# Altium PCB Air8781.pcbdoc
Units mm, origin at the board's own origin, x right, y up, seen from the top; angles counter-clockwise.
Board outline 40.5 x 34.5 mm, 2 copper layers (Top Layer, Bottom Layer); 1 components, 0 nets, 12 pads, 0 vias.
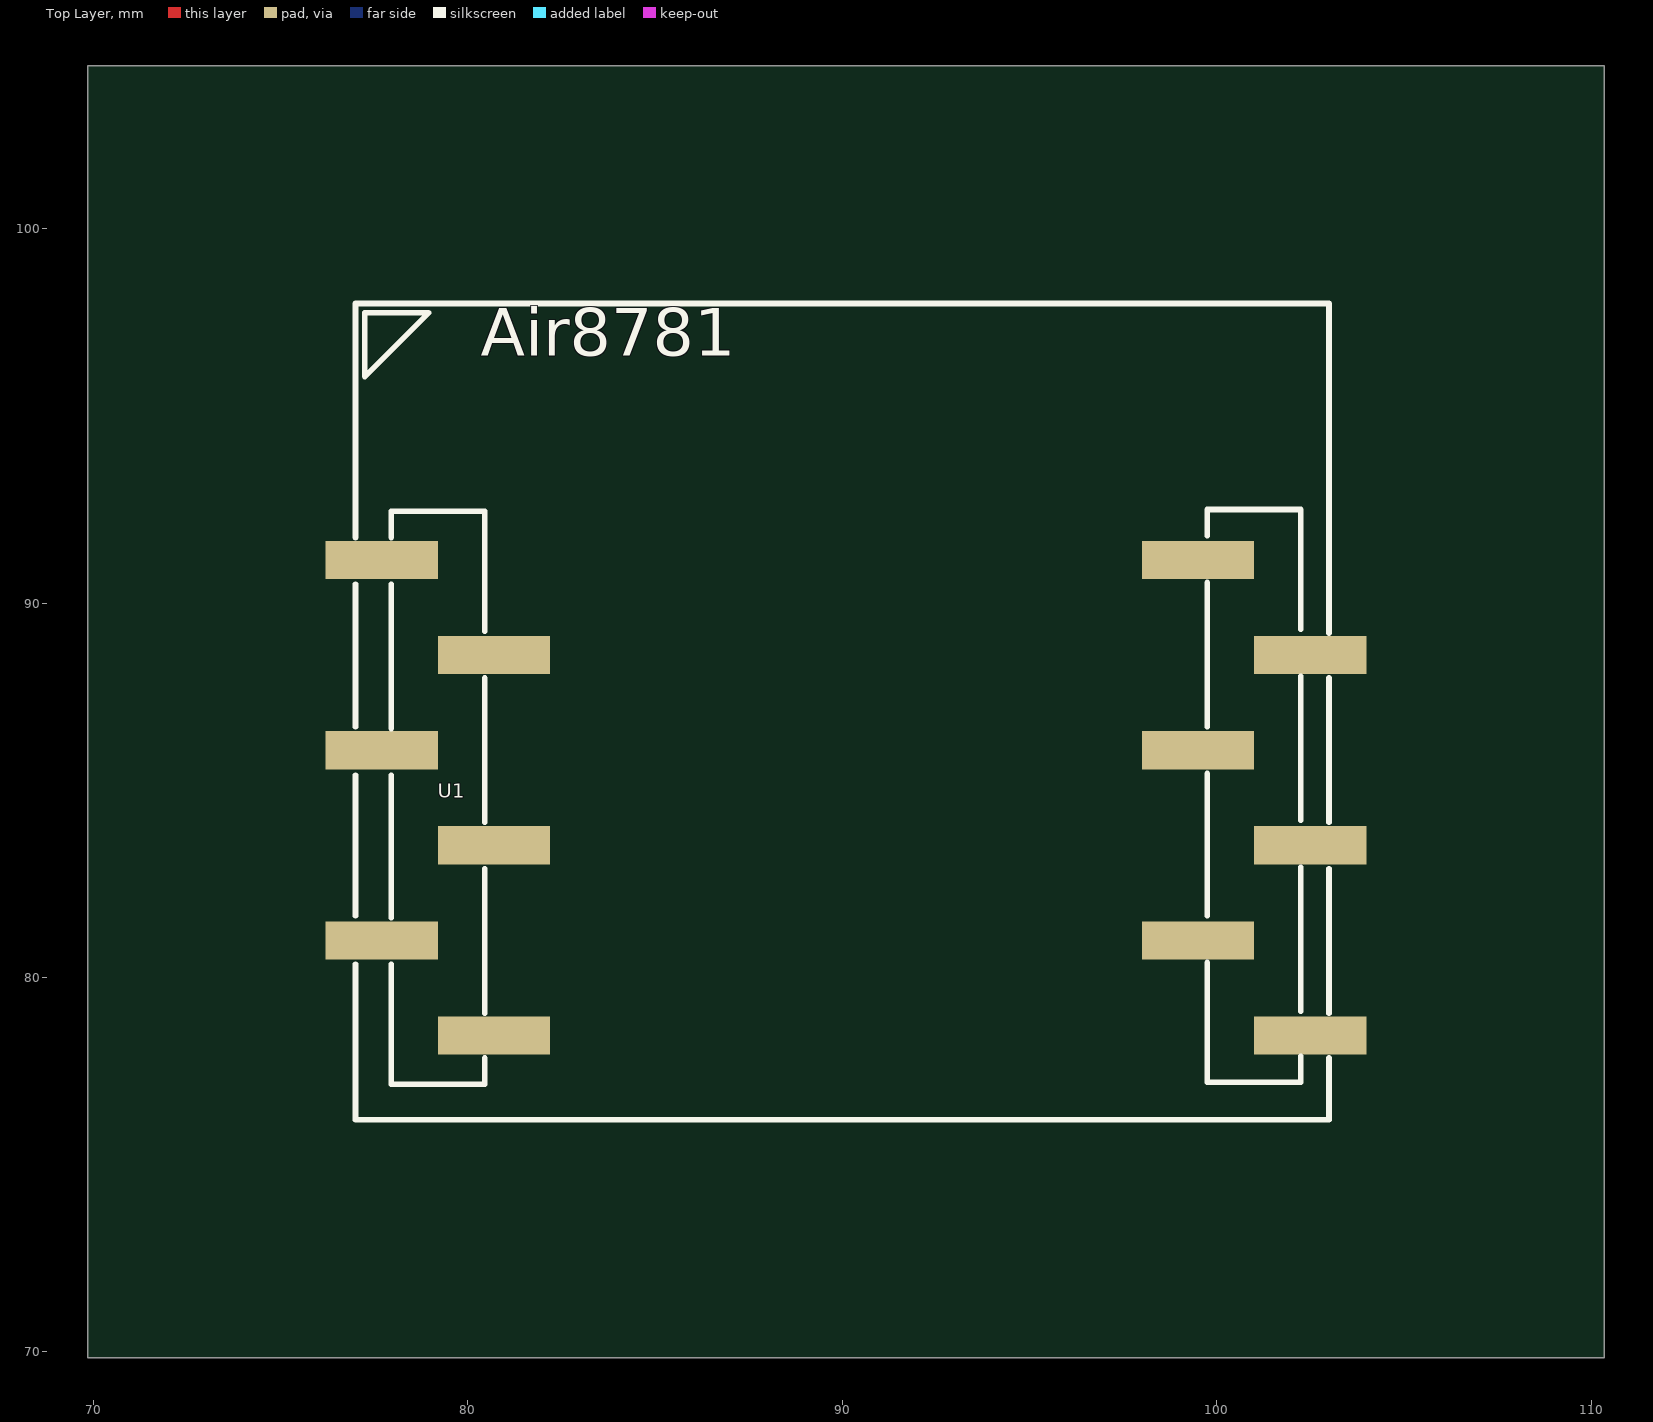
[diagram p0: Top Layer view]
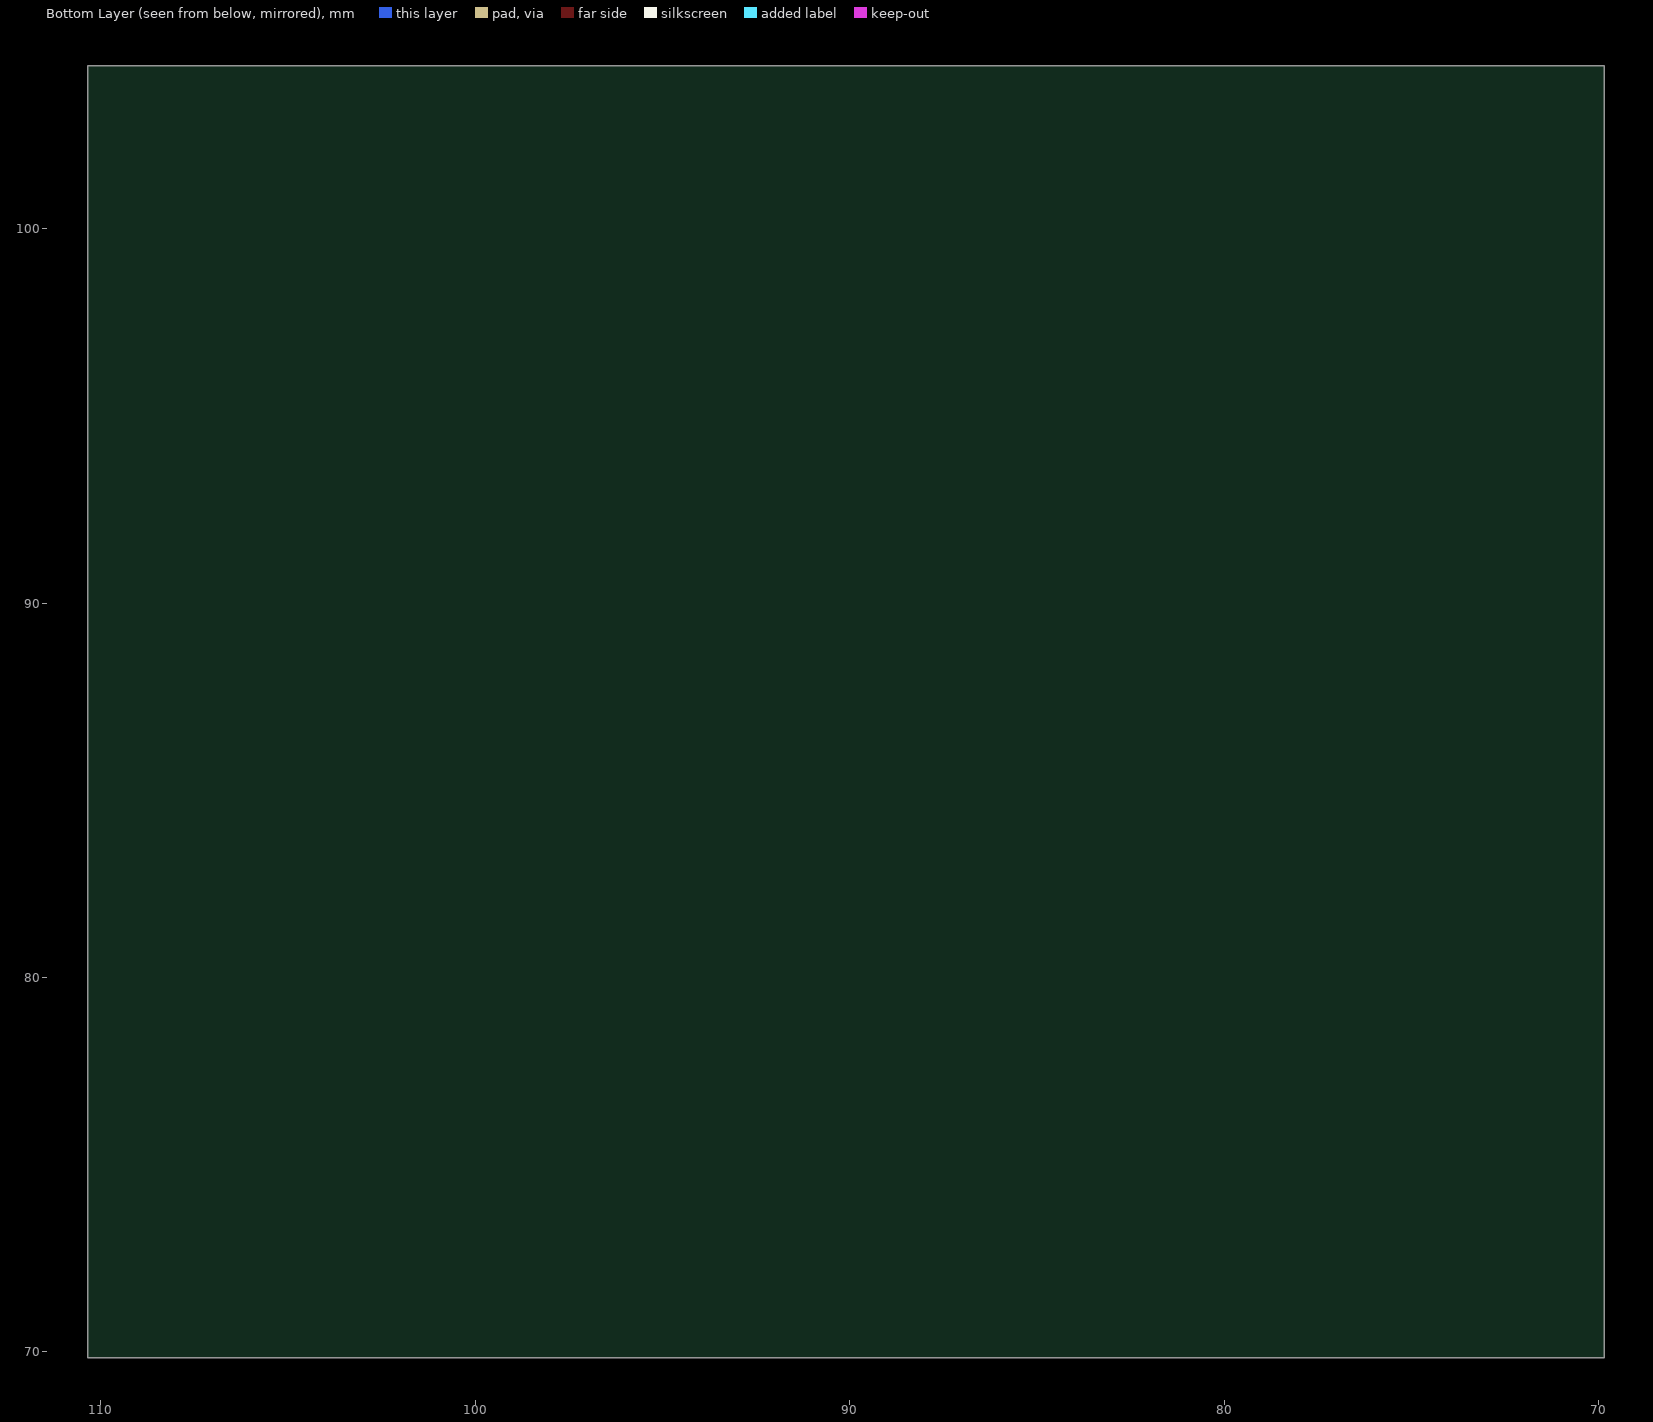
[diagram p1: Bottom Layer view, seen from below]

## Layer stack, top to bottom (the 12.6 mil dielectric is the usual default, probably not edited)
Top Layer: signal copper (thickness not stored)
Dielectric: dielectric 0.32, FR-4, Dk 4.8
Bottom Layer: signal copper (thickness not stored)

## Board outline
110.35,69.85 69.85,69.85 69.85,104.35 110.35,104.35

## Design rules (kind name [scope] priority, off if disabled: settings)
BoardOutlineClearance safeClearance [All] p0: genericclearance=0.254 ignorepadtopadclearanceinfootprint=FALSE except(0: Region-OutlineEdge Poly-OutlineEdge Text-OutlineEdge Sheet-OutlineEdge Hole-OutlineEdge Track-CutoutEdge SMDPad-CutoutEdge THPad-CutoutEdge Via-CutoutEdge Fill-CutoutEdge Region-CutoutEdge Poly-CutoutEdge Text-CutoutEdge Sheet-CutoutEdge Hole-CutoutEdge Arc-SplitContinuation Track-SplitContinuation SMDPad-SplitContinuation THPad-SplitContinuation Via-SplitContinuation Fill-SplitContinuation Poly-SplitContinuation Region-SplitContinuation Text-SplitContinuation; 0.152: Track-OutlineEdge SMDPad-OutlineEdge THPad-OutlineEdge Via-OutlineEdge Fill-OutlineEdge)
Clearance safeClearance [All] p1: gap=0.178 ignorepadtopadclearanceinfootprint=FALSE except(0: Region-Track Poly-Track Region-SMDPad Poly-SMDPad Region-THPad Poly-THPad Region-Via Poly-Via Region-Fill Poly-Fill Text-Fill Track-Region SMDPad-Region THPad-Region Via-Region Fill-Region Region-Region Poly-Region Text-Region Sheet-Region Hole-Region Track-Poly SMDPad-Poly THPad-Poly Via-Poly Fill-Poly Region-Poly Poly-Poly Text-Poly Sheet-Poly Hole-Poly Fill-Text Region-Text Poly-Text Text-Text Sheet-Text Hole-Text Region-Sheet Poly-Sheet Text-Sheet Sheet-Sheet Hole-Sheet Region-Hole Poly-Hole Text-Hole Sheet-Hole; 0.152: Track-Track SMDPad-Track THPad-Track Via-Track Fill-Track Text-Track Sheet-Track Hole-Track Track-SMDPad SMDPad-SMDPad THPad-SMDPad Via-SMDPad Fill-SMDPad Text-SMDPad Sheet-SMDPad Hole-SMDPad Track-THPad SMDPad-THPad THPad-THPad Via-THPad Fill-THPad Text-THPad Sheet-THPad Hole-THPad Track-Via SMDPad-Via THPad-Via Via-Via Fill-Via Text-Via Sheet-Via Hole-Via Track-Fill SMDPad-Fill THPad-Fill Via-Fill Fill-Fill Sheet-Fill Hole-Fill Track-Text SMDPad-Text THPad-Text Via-Text Track-Sheet SMDPad-Sheet THPad-Sheet Via-Sheet Fill-Sheet Track-Hole SMDPad-Hole THPad-Hole Via-Hole Fill-Hole Hole-Hole)
PasteMaskExpansion Common [All] p1: expansion=0
SolderMaskExpansion Common [All] p1: useseparateexpansions=TRUE expansion=0 expansionbottom=0
Width trackWidth [All] p1: maxlimit=12 minlimit=12 preferedwidth=12

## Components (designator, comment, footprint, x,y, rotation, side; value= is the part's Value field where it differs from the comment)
U1 "AIR8781" AIR8781 79.2,84.8 r0 top

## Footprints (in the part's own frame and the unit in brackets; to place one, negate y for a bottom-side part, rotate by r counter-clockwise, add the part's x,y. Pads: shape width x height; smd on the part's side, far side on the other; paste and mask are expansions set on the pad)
AIR8781 [mm]
  rect 3x1.02 smd: 1(-1.5,6.35) 2(1.5,3.81) 3(-1.5,1.27) 4(1.5,-1.27) 5(-1.5,-3.81) 6(1.5,-6.35) 7(23.3,-6.35) 8(20.3,-3.81) 9(23.3,-1.27) 10(20.3,1.27) 11(23.3,3.81) 12(20.3,6.35)
  silkscreen extent -2.2,-8.6 23.8,13.2

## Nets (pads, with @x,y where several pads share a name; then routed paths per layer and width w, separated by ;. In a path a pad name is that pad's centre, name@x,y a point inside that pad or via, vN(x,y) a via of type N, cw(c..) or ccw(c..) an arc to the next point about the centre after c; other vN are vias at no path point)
pads on no net: U1.1 U1.2 U1.3 U1.4 U1.5 U1.6 U1.7 U1.8 U1.9 U1.10 U1.11 U1.12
